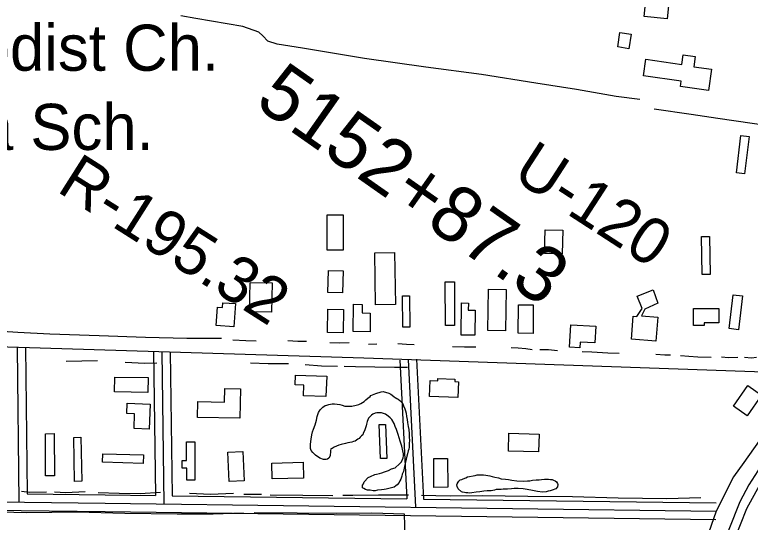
# Model space of a CAD drawing. Extents: x 3324104 to 3361979, y 612876 to 638273.
# Drawn here: x 3331289 to 3332612, y 621562 to 622475 of the extents above; entities that cross this region are included whole.
import ezdxf

# ---------------------------------------------------------------- set-up
doc = ezdxf.new("R2010")
doc.units = 0
for name, color, linetype in [('V-BLDG-IDEN', 7, 'Continuous'), ('V-BLDG-OTLN', 7, 'Continuous'), ('V-LEVE-TOET', 7, 'Continuous'), ('V-RIVR-RANG-IDEN', 7, 'Continuous'), ('V-ROAD-CNTR', 7, 'Continuous'), ('V-SITE-OTLN-IDEN', 7, 'Continuous'), ('V-SITE-VEGE', 7, 'Continuous'), ('V-SURV-IDEN', 7, 'Continuous'), ('V-TOPO-SHOR', 7, 'Continuous')]:
    doc.layers.add(name, color=color, linetype=linetype)

msp = doc.modelspace()

# ---------------------------------------------------------------- linework, layer by layer
at = {"layer": 'V-BLDG-OTLN'}
for points in [[(3332469.1, 622527.1), (3332463, 622467.7), (3332421.3, 622472), (3332426.1, 622519.1), (3332444.3, 622517.2), (3332445.6, 622529.5)], [(3332377.9, 622443.4), (3332397.9, 622440.3), (3332393.8, 622414), (3332373.8, 622417.1)], [(3332487.9, 622355.7), (3332420.2, 622365.4), (3332424.4, 622395.1), (3332489.2, 622385.8), (3332491.7, 622402.8), (3332513.5, 622399.7), (3332510.9, 622381.4), (3332542.5, 622376.9), (3332537, 622339), (3332486.6, 622346.2)], [(3332587.4, 622190.9), (3332595.7, 622257.7), (3332610.6, 622255.8), (3332602.3, 622189)], [(3331851.2, 622051.2), (3331851.2, 622115.1), (3331880, 622115.1), (3331880, 622051.2)], [(3332242.1, 622045.6), (3332243.2, 622088.3), (3332274.9, 622087.5), (3332273.8, 622044.8)], [(3332539.1, 622076), (3332540, 622007.9), (3332525.7, 622007.7), (3332524.8, 622075.8)], [(3331938.2, 621953), (3331936.6, 622046.7), (3331972.2, 622047.3), (3331973.8, 621953.6)], [(3331852.2, 621975.1), (3331853.3, 622015), (3331879.9, 622014.3), (3331878.8, 621974.4)], [(3331752, 621992.5), (3331751, 621939.6), (3331711.3, 621940.4), (3331712.3, 621993.2)], [(3332063.6, 621915.9), (3332063.5, 621994.3), (3332079.8, 621994.3), (3332079.9, 621915.9)], [(3332173, 621980.7), (3332171.7, 621906.5), (3332140, 621907), (3332141.3, 621981.2)], [(3331987.1, 621912.6), (3331986.7, 621969.1), (3331999.2, 621969.2), (3331999.6, 621912.7)], [(3332446, 621930.7), (3332442.6, 621887.5), (3332398.6, 621891), (3332401.9, 621932.7), (3332408.3, 621932.2), (3332417.6, 621946.7), (3332409.1, 621968.4), (3332437.8, 621979.8), (3332446.3, 621956.2), (3332422.7, 621945.4), (3332416.5, 621933)], [(3332574.6, 621910.3), (3332581.6, 621971.1), (3332598.4, 621969.1), (3332591.4, 621908.3)], [(3331683, 621913.6), (3331651.4, 621915.7), (3331653.6, 621949), (3331662.7, 621948.4), (3331663.3, 621956.9), (3331685.8, 621955.4)], [(3332117.2, 621943.2), (3332116.6, 621898.2), (3332091.8, 621898.5), (3332092.6, 621956.5), (3332105.1, 621956.3), (3332104.9, 621943.3)], [(3331851.4, 621903.3), (3331852, 621945), (3331880.3, 621944.6), (3331879.7, 621902.8)], [(3331897.7, 621905), (3331898.3, 621954.1), (3331914.1, 621953.9), (3331913.9, 621938.5), (3331928.6, 621938.3), (3331928.2, 621904.6)], [(3332221.9, 621953.2), (3332221.8, 621901.7), (3332194.9, 621901.8), (3332195, 621953.2)], [(3332510.3, 621946.4), (3332555.8, 621946.3), (3332555.7, 621920.7), (3332529.5, 621920.8), (3332529.5, 621915.9), (3332510.2, 621916)], [(3332289.4, 621917.1), (3332334.4, 621914.6), (3332332.7, 621884.7), (3332306.4, 621886.1), (3332305.8, 621875.7), (3332287.2, 621876.7)], [(3331468.5, 621823.1), (3331528.8, 621822.1), (3331528.4, 621795.4), (3331468.1, 621796.4)], [(3331794, 621826.8), (3331850.1, 621824.9), (3331848.8, 621787.9), (3331808.2, 621789.3), (3331808.9, 621808.8), (3331793.4, 621809.3)], [(3332086.3, 621786.2), (3332035.3, 621788.2), (3332036.4, 621816.9), (3332049.9, 621816.4), (3332050.1, 621820.3), (3332080.6, 621819.1), (3332080.4, 621815), (3332087.4, 621814.7)], [(3331693.9, 621749.1), (3331617.4, 621750.4), (3331617.9, 621779), (3331666.2, 621778.1), (3331666.6, 621802.5), (3331694.8, 621802)], [(3332582.1, 621770.8), (3332608.2, 621808.1), (3332632.8, 621790.8), (3332606.6, 621753.5)], [(3331491.1, 621776), (3331532.4, 621774.4), (3331530.7, 621729.4), (3331503.3, 621730.4), (3331504.3, 621756.9), (3331490.4, 621757.4)], [(3331955.9, 621738), (3331958.2, 621676.8), (3331947, 621676.4), (3331944.7, 621737.6)], [(3331344.2, 621645.3), (3331343.7, 621721.2), (3331359.5, 621721.3), (3331360.1, 621645.5)], [(3332178.1, 621722), (3332232.4, 621720.5), (3332231.5, 621688.4), (3332177.3, 621689.9)], [(3331407.8, 621714.7), (3331409.1, 621635.5), (3331396.1, 621635.3), (3331394.8, 621714.5)], [(3331612.6, 621706.4), (3331612.6, 621637.7), (3331598.2, 621637.7), (3331598.2, 621659.4), (3331590.2, 621659.4), (3331590.2, 621672.8), (3331598, 621672.8), (3331598, 621706.4)], [(3331447.2, 621685.2), (3331520.5, 621683), (3331520, 621667.8), (3331446.8, 621670.1)], [(3331699.4, 621689.4), (3331701.7, 621636.5), (3331674.4, 621635.4), (3331672.2, 621688.2)], [(3332067.6, 621676.7), (3332068, 621624.8), (3332043, 621624.6), (3332042.6, 621676.5)], [(3331751.5, 621668.4), (3331807.6, 621669.7), (3331808.3, 621641.2), (3331752.2, 621639.9)]]:
    msp.add_lwpolyline(points, close=True, dxfattribs=at)
at = {"layer": 'V-LEVE-TOET'}
msp.add_lwpolyline([(3332629.2, 621628.5), (3332605.4, 621586.1), (3332583.1, 621528.3), (3332567, 621462.8), (3332556.7, 621386.4), (3332549.2, 621278.2), (3332541.9, 621144.3), (3332531.9, 620980.2)], dxfattribs=at)
at = {"layer": 'V-ROAD-CNTR'}
for points in [[(3335801.6, 625083.2), (3334881.1, 624260.2), (3334472.9, 623895.9), (3334358, 623790.3), (3334255.1, 623697.1), (3334200.7, 623647.7), (3334152.3, 623600.3), (3334077.2, 623518.6), (3333606.7, 622932.8), (3332948.8, 622115.4), (3332638.7, 621722.9), (3332601.1, 621669.5), (3332582.1, 621643.4), (3332550.9, 621581.9), (3332533.2, 621530.4), (3332516.7, 621467.3), (3332503.8, 621368.2), (3332484.7, 621134.9), (3332435.8, 620389.6)], [(3333016.8, 622200.4), (3333011.1, 622204), (3333005.3, 622207.5), (3332999.4, 622210.7), (3332993.4, 622213.7), (3332987.4, 622216.5), (3332981.2, 622219.1), (3332974.9, 622221.4), (3332968.5, 622223.6), (3332962.1, 622225.5), (3332955.6, 622227.2), (3332949.1, 622228.6), (3332855.4, 622244.4), (3332710.7, 622265.7), (3332553.8, 622288.5), (3332505.9, 622295.6), (3332439.4, 622305.2)], [(3332722.7, 621829.2), (3331917.1, 621857.3), (3329994.2, 621916.4), (3328221.8, 621973.8)], [(3331292.9, 621876.5), (3331296.2, 621597.9)], [(3331307.9, 621876.7), (3331311.1, 621612.7)], [(3331538.4, 621868.3), (3331541.8, 621609.8)], [(3331553.4, 621868.5), (3331557, 621594.6)], [(3331568.4, 621868.7), (3331571.9, 621609.4)], [(3331981.9, 621853.8), (3331994.1, 621604)], [(3331996.8, 621854.5), (3332009.8, 621588.7)], [(3332011.8, 621855.2), (3332024.1, 621603.6)], [(3331311.1, 621612.7), (3331451.5, 621611), (3331541.8, 621609.8)], [(3330436.4, 621608.8), (3331451.3, 621596), (3332550.8, 621581.8)], [(3331571.9, 621609.4), (3331994.1, 621604)], [(3332024.1, 621603.6), (3332551, 621596.8)], [(3330795.1, 621589.2), (3331451.2, 621581), (3332550.6, 621566.8)]]:
    msp.add_lwpolyline(points, dxfattribs=at)
at = {"layer": 'V-SITE-VEGE'}
for points in [[(3331940.1, 621758.6), (3331937.5, 621758), (3331933.2, 621756.4), (3331930.6, 621754.3), (3331925.3, 621748.9), (3331924.3, 621746.3), (3331923.2, 621743.1), (3331921.7, 621738.3), (3331921.2, 621735.1), (3331920.1, 621731.9), (3331918.6, 621728.1), (3331915.9, 621721.8), (3331915.4, 621719.1), (3331912.8, 621717.5), (3331910.2, 621714.8), (3331908.6, 621712.7), (3331905.9, 621711.1), (3331901.2, 621707.8), (3331898.5, 621707.3), (3331895.3, 621706.2), (3331891.6, 621705.1), (3331887.9, 621704.5), (3331883.7, 621703.5), (3331876.2, 621701.8), (3331872, 621700.7), (3331863.5, 621696.9), (3331859.8, 621694.8), (3331857.7, 621693.7), (3331856.7, 621690.5), (3331856.7, 621686.8), (3331856.2, 621684.1), (3331856.2, 621681.5), (3331854.1, 621677.2), (3331851.5, 621675.1), (3331849.3, 621674.5), (3331844.5, 621674.5), (3331837.6, 621677.1), (3331830.1, 621682.3), (3331825.3, 621687.1), (3331822.1, 621690.8), (3331821, 621694.5), (3331821, 621702.5), (3331822, 621711.5), (3331823.5, 621719), (3331824.5, 621724.8), (3331826.6, 621729.6), (3331829.2, 621737.1), (3331830.3, 621741.3), (3331831.8, 621745.6), (3331832.8, 621752), (3331833.9, 621755.7), (3331835.4, 621759.4), (3331838.6, 621764.2), (3331843.3, 621769.1), (3331847.6, 621771.7), (3331850.2, 621772.8), (3331853.9, 621773.9), (3331859.8, 621775), (3331864, 621775.1), (3331873.6, 621773.5), (3331877.9, 621772.5), (3331882.6, 621770.9), (3331890.1, 621770.5), (3331895.4, 621771), (3331903.4, 621772.7), (3331908.1, 621773.8), (3331911.8, 621775.4), (3331917.7, 621779.2), (3331920.8, 621782.4), (3331924, 621785), (3331928.2, 621788.3), (3331929.8, 621789.9), (3331938.3, 621793.7), (3331948.4, 621796.4), (3331951.5, 621796.9), (3331962.2, 621794.3), (3331965.4, 621792.2), (3331968.1, 621790.7), (3331971.3, 621787.5), (3331973.4, 621786.5), (3331976.6, 621784.4), (3331978.7, 621783.3), (3331981.9, 621780.7), (3331984.6, 621778), (3331987.3, 621774.9), (3331988.4, 621771.2), (3331990.6, 621765.9), (3331992.2, 621762.2), (3331993.3, 621758.4), (3331993.8, 621752.1), (3331994.9, 621746.8), (3331995.5, 621741.5), (3331996.6, 621734), (3331997.7, 621728.7), (3331998.3, 621720.7), (3331998.4, 621714.9), (3331998.9, 621709.1), (3331998.4, 621704.3), (3331998.5, 621696.8), (3331998, 621693.6), (3331996.9, 621690.4)], [(3331996.9, 621690.4), (3331995.4, 621685.1), (3331994.4, 621680.9), (3331991.8, 621670.2), (3331990.7, 621664.9), (3331988.2, 621653.2), (3331986.1, 621648.4), (3331985.6, 621644.7), (3331983.5, 621639.3), (3331981.9, 621636.1), (3331980.3, 621633.5), (3331977.2, 621629.2), (3331974.5, 621627.1), (3331971.4, 621624.9), (3331966.6, 621623.8), (3331957.1, 621621.1), (3331953.3, 621620.5), (3331948.6, 621620), (3331941.7, 621619.4), (3331937.4, 621618.3), (3331933.7, 621618.3), (3331928.4, 621619.8), (3331923.6, 621619.8), (3331919.9, 621620.8), (3331917.2, 621622.4), (3331914.5, 621624), (3331914.5, 621628.7), (3331916.1, 621630.9), (3331917.6, 621634.6), (3331925, 621642.1), (3331928.7, 621644.3), (3331936.7, 621647.5), (3331939.9, 621648.1), (3331945.2, 621649.7), (3331949.4, 621650.8), (3331954.2, 621652.4), (3331961.1, 621655.1), (3331966.9, 621657.8), (3331973.2, 621660), (3331981.2, 621667), (3331984.9, 621670.7), (3331988, 621677.6), (3331988.5, 621681.4), (3331988.5, 621685.1), (3331987.4, 621690.4), (3331985.2, 621698.9), (3331982.5, 621707.9), (3331980.8, 621713.7), (3331978.7, 621719.5), (3331975.9, 621728.6), (3331973.2, 621733.9), (3331971.6, 621739.7), (3331967.3, 621746.6), (3331964.6, 621749.7), (3331960.9, 621752.9), (3331956.1, 621756.6), (3331948.6, 621758.7), (3331940.1, 621758.6)]]:
    msp.add_lwpolyline(points, dxfattribs=at)
msp.add_lwpolyline([(3332086.7, 621622), (3332084.6, 621626.2), (3332084.5, 621628.9), (3332085, 621631), (3332086.6, 621633.7), (3332087.7, 621635.8), (3332090.3, 621638), (3332093, 621638.5), (3332095.6, 621640.1), (3332100.4, 621641.8), (3332103.6, 621643.4), (3332107.3, 621643.9), (3332113.6, 621645.6), (3332117.4, 621646.1), (3332121.1, 621647.2), (3332132.2, 621647.3), (3332136.5, 621646.3), (3332143.4, 621645.3), (3332147.7, 621644.2), (3332152.4, 621642.7), (3332159.4, 621641.7), (3332164.2, 621640.1), (3332172.1, 621639.1), (3332177.5, 621638.6), (3332183.3, 621637.6), (3332192.3, 621636.6), (3332204, 621635.6), (3332211.5, 621636.2), (3332215.7, 621636.2), (3332220.5, 621637.3), (3332226.9, 621637.9), (3332232.2, 621637.9), (3332236.4, 621638.5), (3332242.3, 621639.1), (3332249.2, 621639.1), (3332252.9, 621638.6), (3332255.6, 621638.6), (3332258.2, 621637.6), (3332261.4, 621636.5), (3332263.6, 621634.4), (3332265.7, 621631.8), (3332266.3, 621629.7), (3332265.2, 621625.4), (3332262.6, 621622.2), (3332260.5, 621621.1), (3332257.8, 621620), (3332252.5, 621618.4), (3332248.8, 621617.9), (3332245.1, 621616.8), (3332238.2, 621616.2), (3332229.2, 621617.2), (3332220.6, 621618.7), (3332211.1, 621620.8), (3332203.6, 621621.8), (3332194.6, 621622.8), (3332187.7, 621622.7), (3332182.9, 621622.2), (3332175.4, 621621.6), (3332167.5, 621621.5), (3332164.3, 621621), (3332155.3, 621620.9), (3332152.1, 621619.3), (3332146.2, 621618.2), (3332138.8, 621618.1), (3332133, 621617.6), (3332125.5, 621616.4), (3332119.2, 621615.9), (3332111.2, 621614.7), (3332106.4, 621614.2), (3332103.8, 621614.7), (3332100.6, 621614.7), (3332097.9, 621615.2), (3332094.7, 621615.7), (3332092.6, 621616.7)], close=True, dxfattribs=at)
at = {"layer": 'V-TOPO-SHOR'}
for p, q in [((3331940.4, 621882.3), (3331925.5, 621881.8)), ((3331437.7, 621852.2), (3331381, 621851.4)), ((3331732.5, 621611.5), (3331700.8, 621611.7))]:
    msp.add_line(p, q, dxfattribs=at)
for points in [[(3332413.4, 622322.3), (3332371.2, 622328.1), (3332299.9, 622340.3), (3332226.7, 622351.7), (3332128.9, 622367.4), (3332028.5, 622380.5), (3331918, 622396.5), (3331806.3, 622414.7), (3331761.2, 622422.2), (3331744.3, 622427.3), (3331735.3, 622437), (3331727.8, 622443.6), (3331699, 622453.9), (3331614.3, 622468.2), (3331587.6, 622473)], [(3332986, 622123.4), (3332943.2, 622063.5), (3332887, 621991.5), (3332833.8, 621924.8), (3332773.2, 621852.7), (3332727.4, 621796.5), (3332674.2, 621724.5), (3332642.4, 621679.5), (3332610, 621629.4), (3332593.8, 621598.7), (3332574, 621548.6), (3332550.7, 621469.4), (3332539.9, 621417.1), (3332533.7, 621346.9), (3332522.9, 621191.8), (3332508.8, 620979.1), (3332504.8, 620912)], [(3331661, 621892.4), (3331598.6, 621892.3), (3331524, 621894.3), (3331440.7, 621897.4), (3331352, 621900.5), (3331294.4, 621903.4), (3331266.5, 621905.3)], [(3331723.2, 621887.8), (3331704.7, 621888.1), (3331680.9, 621889.2)], [(3331814, 621886.8), (3331798, 621887.1), (3331780, 621888.2)], [(3331890.6, 621884.9), (3331873, 621884.3), (3331855.8, 621884.6)], [(3332007.5, 621881.2), (3331994, 621881.5), (3331978.1, 621883)], [(3332118.2, 621876.6), (3332098, 621876.8), (3332076.3, 621877.5)], [(3332219.7, 621872.3), (3332208.3, 621873.9), (3332194.6, 621875), (3332182, 621875.4)], [(3332265.7, 621870.2), (3332249.3, 621872.1), (3332233.4, 621872)], [(3332376.4, 621865.2), (3332355.9, 621866.2), (3332327.3, 621868.1), (3332310.1, 621868.4)], [(3332468.8, 621862.5), (3332458.7, 621862.4), (3332442.3, 621863.6)], [(3331544.4, 621847.9), (3331522.5, 621847.7), (3331487.3, 621849.5)], [(3332542.2, 621858.5), (3332518.3, 621858.7), (3332501.8, 621860.2), (3332486.7, 621861)], [(3332589.9, 621858), (3332573.5, 621857.4), (3332560.4, 621858.6)], [(3332623.4, 621858.2), (3332614.5, 621856.9), (3332601.9, 621858.1)], [(3331781.5, 621847.1), (3331745, 621846.8), (3331712.9, 621848.4)], [(3331869.4, 621842.3), (3331840.8, 621842.9), (3331811.3, 621845.2)], [(3331995.5, 621840.1), (3331972.1, 621840.1), (3331936.9, 621841.1), (3331902.1, 621841.3), (3331881.4, 621842.4)], [(3331345.8, 621615.8), (3331315.2, 621615.6), (3331300.7, 621617.4)], [(3331415.1, 621616.7), (3331380.8, 621615), (3331360.3, 621615.9)], [(3331550.9, 621615.4), (3331514.3, 621612.9), (3331476.7, 621613.4), (3331439, 621615)], [(3331682.1, 621613.4), (3331641.1, 621611.6), (3331603.1, 621613.6)], [(3331861.1, 621609.5), (3331807.4, 621609.8), (3331748.5, 621610.5)], [(3331997.2, 621610.4), (3331943.1, 621610.4), (3331897.3, 621609.7), (3331879.4, 621610)], [(3331700.1, 621577.9), (3331646, 621576.5), (3331581, 621576.1), (3331486.5, 621577.5), (3331401.1, 621580.2), (3331309.9, 621578.7), (3331239.9, 621580.3), (3331149.1, 621585), (3331039.7, 621587.9), (3330955.2, 621589.4), (3330855.7, 621592.4), (3330765.3, 621594.7), (3330678.3, 621594.9), (3330594.6, 621595.5), (3330522.1, 621597.1), (3330454.1, 621598.3), (3330411.4, 621599.2), (3330377.9, 621600.6), (3330347.5, 621600.6)], [(3332523.3, 621605.6), (3332462.2, 621603.7), (3332374.5, 621605.3), (3332292.5, 621607.7), (3332212.3, 621607.9), (3332130.3, 621609.1), (3332072.5, 621608.7), (3332020.7, 621609.9)], [(3332480.7, 621381.5), (3332452.5, 621383.4), (3332394, 621388), (3332343.5, 621385.1), (3332284.2, 621386.8), (3332237.8, 621386), (3332155.8, 621388.7), (3332089.5, 621388.3), (3332039.8, 621387.5), (3332025.7, 621389.5), (3332010.3, 621392.3), (3332002.4, 621396.3), (3331997.4, 621405), (3331995.2, 621424.5), (3331992.2, 621493.2), (3331990.5, 621556.2), (3331989.9, 621576.5), (3331931.1, 621578.2), (3331866.9, 621577.3), (3331796.8, 621578.4), (3331719.6, 621578.9)]]:
    msp.add_lwpolyline(points, dxfattribs=at)

# ---------------------------------------------------------------- texts
at = {"layer": 'V-BLDG-IDEN'}
msp.add_text('Bayou Goula Sch.', height=83, dxfattribs=at).set_placement((3330644.1, 622231.8))
at = {"layer": 'V-RIVR-RANG-IDEN'}
for s, rotation, p in [('U-120', 327.0228, (3332181.3, 622181.9)), ('R-195.32', 327.5942, (3331362, 622158.4))]:
    msp.add_text(s, height=83, rotation=rotation, dxfattribs=at).set_placement(p)
at = {"layer": 'V-SITE-OTLN-IDEN'}
msp.add_text('St. Luke Methodist Ch.', height=83, rotation=359.9873, dxfattribs=at).set_placement((3330533.5, 622374.5))
at = {"layer": 'V-SURV-IDEN'}
msp.add_text('5152+87.3', height=100, rotation=324.9472, dxfattribs=at).set_placement((3331718, 622312.6))

doc.saveas('drawing.dxf')
